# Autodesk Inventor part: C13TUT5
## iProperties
Created: 2005-03
Part Number: C13TUT5
Document SubType Name: Modeling
Designer: CADCIM
Manufacturer: Standard
Standards Organization: Custom
Density: 1 g/cm^3
Author: CADCIM
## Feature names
1. Split1
2. Split2
3. Split3
4. Split4
5. Split5
6. Fillet1
